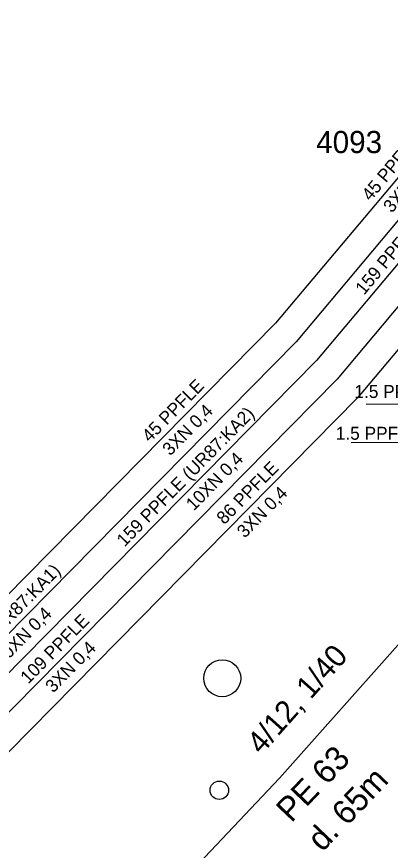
# Model space of a CAD drawing. Extents: x -756413 to -755757, y -1139003 to -1138237.
# Drawn here: x -756305.56 to -756295.44, y -1138392.04 to -1138369.48 of the extents above; entities that cross this region are included whole.
import ezdxf

# ---------------------------------------------------------------- set-up
doc = ezdxf.new("R2010")
doc.units = 0
for name, color, linetype in [('f001_pol_texty', 7, 'Continuous'), ('f002_inz_znacky_mimo_TO2', 7, 'Continuous'), ('f004_popis_kab_zil', 7, 'Continuous'), ('f006_osa_trasy', 7, 'Continuous'), ('f006_stp_linie', 7, 'Continuous'), ('f006_stp_texty', 7, 'Continuous'), ('f307_kabel_metal', 7, 'Continuous'), ('f307_kabel_metal_ann', 7, 'Continuous'), ('f373_cerch_cara', 7, 'Continuous')]:
    doc.layers.add(name, color=color, linetype=linetype)

msp = doc.modelspace()

# ---------------------------------------------------------------- linework, layer by layer
at = {"layer": 'f002_inz_znacky_mimo_TO2'}
for centre, radius in [((-756299.99, -1138387.38), 0.5), ((-756300.07, -1138390.41), 0.25)]:
    msp.add_circle(centre, radius, dxfattribs=at)
at = {"layer": 'f006_osa_trasy'}
msp.add_lwpolyline([(-756312.22, -1138404.34), (-756311.43, -1138403.06), (-756307.8, -1138399.78), (-756302.65, -1138394.53), (-756298.44, -1138390.08), (-756293.77, -1138384.84), (-756291.02, -1138381.91), (-756287.55, -1138377.18), (-756286, -1138374.68), (-756285.31, -1138374.59), (-756283.34, -1138375.8)], dxfattribs=at)
at = {"layer": 'f006_stp_linie'}
msp.add_lwpolyline([(-756325.53, -1138418.96), (-756324.32, -1138416.51), (-756322.61, -1138413.84), (-756321.49, -1138412.22), (-756320.41, -1138411.21), (-756318.19, -1138409.32), (-756315.85, -1138407.31), (-756315.25, -1138406.9), (-756313.95, -1138405.81), (-756312.72, -1138405.17), (-756312.44, -1138404.71), (-756312.22, -1138404.34), (-756311.43, -1138403.06), (-756307.8, -1138399.78), (-756302.65, -1138394.53), (-756298.44, -1138390.08), (-756293.77, -1138384.84), (-756291.02, -1138381.91), (-756287.55, -1138377.18), (-756286, -1138374.68), (-756285.31, -1138374.59), (-756283.34, -1138375.8), (-756282.74, -1138376.16)], dxfattribs=at)
at = {"layer": 'f307_kabel_metal'}
for points in [[(-756284.683, -1138375.264), (-756284.676, -1138375.255), (-756291.577, -1138369.478), (-756295.006, -1138373.564), (-756295.13, -1138373.711), (-756298.544, -1138377.773), (-756318.688, -1138398.187), (-756319.519, -1138397.43)], [(-756285.765, -1138375.387), (-756285.733, -1138375.348), (-756291.484, -1138370.534), (-756294.432, -1138374.047), (-756294.556, -1138374.194), (-756297.989, -1138378.278), (-756318.66, -1138399.227), (-756319.205, -1138399.742), (-756330.074, -1138410.117), (-756326.605, -1138419.746), (-756341.343, -1138432.472)], [(-756286.972, -1138375.658), (-756286.816, -1138375.476), (-756291.179, -1138371.724), (-756291.391, -1138371.59), (-756293.858, -1138374.53), (-756293.982, -1138374.677), (-756297.434, -1138378.783), (-756318.135, -1138399.763), (-756318.689, -1138400.286), (-756329.203, -1138410.322), (-756325.725, -1138419.977), (-756325.47, -1138420.682), (-756325.148, -1138421.576), (-756313.125, -1138448.388), (-756305.964, -1138469.586), (-756306.39, -1138472.389), (-756307.168, -1138474.638), (-756308.162, -1138475.59), (-756309.285, -1138475.849), (-756315.462, -1138479.353)], [(-756288.384, -1138376.174), (-756287.902, -1138375.6), (-756287.847, -1138375.534), (-756291.298, -1138372.646), (-756293.284, -1138375.013), (-756293.408, -1138375.16), (-756296.879, -1138379.289), (-756317.519, -1138400.206), (-756328.332, -1138410.527), (-756324.452, -1138421.295), (-756312.811, -1138447.256), (-756304.831, -1138441.703), (-756301.921, -1138444.882), (-756300.466, -1138443.292)], [(-756288.958, -1138375.692), (-756288.904, -1138375.627), (-756291.205, -1138373.702), (-756292.71, -1138375.496), (-756292.834, -1138375.643), (-756296.324, -1138379.794), (-756316.993, -1138400.741), (-756327.461, -1138410.732), (-756323.756, -1138421.014), (-756320.657, -1138427.925), (-756318.754, -1138427.003), (-756311.742, -1138419.982)]]:
    msp.add_lwpolyline(points, dxfattribs=at)
at = {"layer": 'f373_cerch_cara'}
for points in [[(-756289.406, -1138379.098), (-756290.146, -1138379.966), (-756296.091, -1138379.974)], [(-756288.801, -1138379.683), (-756290.648, -1138380.99), (-756296.497, -1138381.011)]]:
    msp.add_lwpolyline(points, dxfattribs=at)

# ---------------------------------------------------------------- texts
at = {"layer": 'f001_pol_texty'}
msp.add_text(' 4093', height=0.6, dxfattribs=at).set_placement((-756297.67, -1138373.17))
at = {"layer": 'f004_popis_kab_zil'}
msp.add_text('4/12, 1/40', height=0.6, rotation=48.29, dxfattribs=at).set_placement((-756298.93, -1138389.47))
at = {"layer": 'f006_stp_texty'}
for s, p in [('PE 63', (-756298.12, -1138391.31)), ('d. 65m', (-756297.28, -1138392.1))]:
    msp.add_text(s, height=0.65, rotation=46.46, dxfattribs=at).set_placement(p)
at = {"layer": 'f307_kabel_metal_ann'}
for s, rotation, p in [('45 PPFLE', 50, (-756295.977, -1138374.488)), ('159 PPFLE (UR87:KA2)', 50, (-756296.15, -1138377.028)), (' 3XN 0,4', 50, (-756295.48, -1138374.907)), ('45 PPFLE', 45.38, (-756301.953, -1138381.013)), (' 3XN 0,4', 45.38, (-756301.491, -1138381.471)), ('159 PPFLE (UR87:KA2)', 45.38, (-756302.636, -1138383.841)), (' 10XN 0,4', 45.38, (-756300.853, -1138382.96)), ('86 PPFLE', 45.38, (-756299.934, -1138383.239)), (' 3XN 0,4', 45.38, (-756299.472, -1138383.697)), ('85 PPFLE (UR87:KA1)', 45.38, (-756307.7, -1138387.906)), (' 10XN 0,4', 45.38, (-756306.039, -1138387.148)), ('109 PPFLE', 45.38, (-756305.244, -1138387.553)), (' 3XN 0,4', 45.38, (-756304.66, -1138387.887))]:
    msp.add_text(s, height=0.35, rotation=rotation, dxfattribs=at).set_placement(p)
for s, p in [('1.5 PPFLE (UR87:KA2)', (-756296.412, -1138379.796)), ('1.5 PPFLE (UR87:KA1)', (-756296.917, -1138380.926))]:
    msp.add_text(s, height=0.35, dxfattribs=at).set_placement(p)

doc.saveas('drawing.dxf')
